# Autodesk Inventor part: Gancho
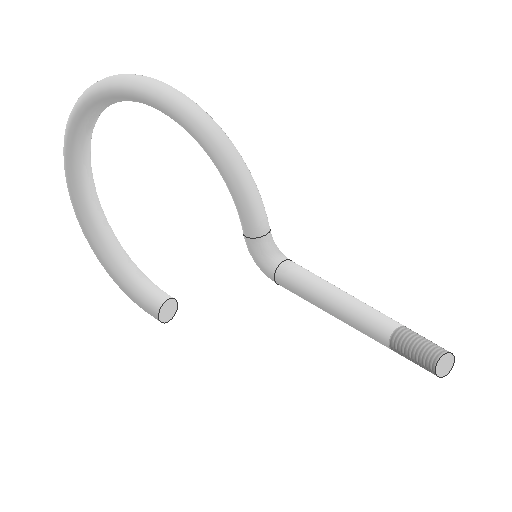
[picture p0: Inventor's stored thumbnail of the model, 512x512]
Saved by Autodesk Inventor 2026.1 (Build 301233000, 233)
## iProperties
Created: 2025-08
Part Number: Gancho
Material: Genérico
Document SubType Name: Modeling
Designer: gianm
Density: 1 g/cm^3
Appearance: Valor por defecto
Author: gianm
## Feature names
1. Barrido1
## Parameters: d0 = 2.5 mm, d1 = 13 mm, d2 = 23 mm, d4 = 0, d5 = 0, d6 = 6 mm, d7 = 0
